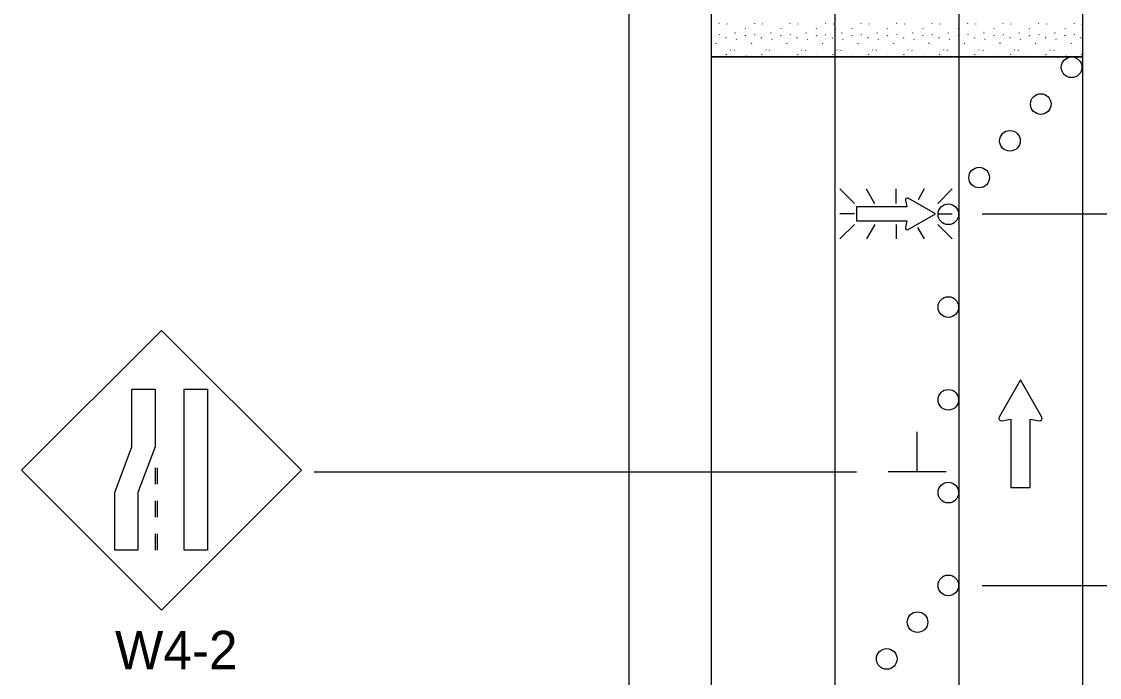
# Model space of a CAD drawing. Extents: x 16742 to 18475, y 7016 to 8203.
# Drawn here: x 16845.6 to 17054.7, y 7838.6 to 7965.9 of the extents above; entities that cross this region are included whole.
import ezdxf

# ---------------------------------------------------------------- set-up
doc = ezdxf.new("R2010")
doc.units = 0
for name, color, linetype in [('ALI_LEGAL_EX', 7, 'Continuous'), ('MT_SCRATCH_LEVEL_A', 7, 'Continuous'), ('MT_SCRATCH_LEVEL_E', 7, 'Continuous'), ('PAVT_EDGE_EX', 7, 'Continuous'), ('TRAFFIC_SIGNS_PR', 7, 'Continuous'), ('TYPICAL_TEXT_DIMEN_PR', 7, 'Continuous')]:
    doc.layers.add(name, color=color, linetype=linetype)

msp = doc.modelspace()

# ---------------------------------------------------------------- linework, layer by layer
at = {"layer": 'ALI_LEGAL_EX'}
for p, q in [((17003.37, 8174.11), (17003.37, 7344.93)), ((17027.37, 8174.11), (17027.37, 7344.93)), ((17051.37, 8174.11), (17051.37, 7344.93)), ((17051.37, 8174.11), (17051.37, 7344.93)), ((17003.37, 8073.55), (17003.37, 7244.36)), ((17027.37, 8073.55), (17027.37, 7244.36)), ((17051.37, 8073.55), (17051.37, 7244.36)), ((17051.37, 8073.55), (17051.37, 7244.36))]:
    msp.add_line(p, q, dxfattribs=at)
for points in [[(17003.37, 7891.2), (17003.37, 7866.2)], [(17027.37, 7891.2), (17027.37, 7866.2)], [(17051.37, 7891.2), (17051.37, 7866.2)]]:
    msp.add_lwpolyline(points, dxfattribs=at)
at = {"layer": 'MT_SCRATCH_LEVEL_A'}
for p, q in [((16979.37, 8103.02), (16979.37, 7959.05)), ((16979.37, 7988.11), (16979.37, 7959.05)), ((16980.86, 7965.57), (16980.91, 7965.5)), ((16982.39, 7965.43), (16982.44, 7965.36)), ((16987.75, 7965.57), (16987.8, 7965.5)), ((16989.28, 7965.43), (16989.33, 7965.36)), ((16994.64, 7965.57), (16994.69, 7965.5)), ((16996.17, 7965.43), (16996.22, 7965.36)), ((17001.53, 7965.57), (17001.58, 7965.5)), ((17003.06, 7965.43), (17003.11, 7965.36)), ((17008.41, 7965.57), (17008.46, 7965.5)), ((17009.94, 7965.43), (17009.99, 7965.36)), ((17015.3, 7965.57), (17015.35, 7965.5)), ((17016.83, 7965.43), (17016.88, 7965.36)), ((17022.19, 7965.57), (17022.24, 7965.5)), ((17023.72, 7965.43), (17023.77, 7965.36)), ((17029.08, 7965.57), (17029.13, 7965.5)), ((17030.6, 7965.43), (17030.66, 7965.36)), ((17035.96, 7965.57), (17036.01, 7965.5)), ((17037.49, 7965.43), (17037.54, 7965.36)), ((17042.85, 7965.57), (17042.9, 7965.5)), ((17044.38, 7965.43), (17044.43, 7965.36)), ((17049.74, 7965.57), (17049.79, 7965.5)), ((17051.27, 7965.43), (17051.32, 7965.36)), ((16980.91, 7963.36), (16980.96, 7963.29)), ((16982.19, 7962.79), (16982.21, 7962.67)), ((16984.03, 7963.65), (16984.08, 7963.76)), ((16985.96, 7964.52), (16986.01, 7964.44)), ((16986, 7963.11), (16986.05, 7963.23)), ((16987.8, 7963.36), (16987.85, 7963.29)), ((16989.08, 7962.79), (16989.09, 7962.67)), ((16990.92, 7963.65), (16990.97, 7963.76)), ((16992.85, 7964.52), (16992.9, 7964.44)), ((16992.89, 7963.11), (16992.94, 7963.23)), ((16994.69, 7963.36), (16994.74, 7963.29)), ((16995.97, 7962.79), (16995.98, 7962.67)), ((16997.81, 7963.65), (16997.86, 7963.76)), ((16999.73, 7964.52), (16999.79, 7964.44)), ((16999.78, 7963.11), (16999.83, 7963.23)), ((17001.57, 7963.36), (17001.62, 7963.29)), ((17002.85, 7962.79), (17002.87, 7962.67)), ((17004.7, 7963.65), (17004.75, 7963.76)), ((17006.62, 7964.52), (17006.67, 7964.44)), ((17006.66, 7963.11), (17006.72, 7963.23)), ((17008.46, 7963.36), (17008.51, 7963.29)), ((17009.74, 7962.79), (17009.76, 7962.67)), ((17011.58, 7963.65), (17011.64, 7963.76)), ((17013.51, 7964.52), (17013.56, 7964.44)), ((17013.55, 7963.11), (17013.6, 7963.23)), ((17015.35, 7963.36), (17015.4, 7963.29)), ((17016.63, 7962.79), (17016.64, 7962.67)), ((17018.47, 7963.65), (17018.52, 7963.76)), ((17020.4, 7964.52), (17020.45, 7964.44)), ((17020.44, 7963.11), (17020.49, 7963.23)), ((17022.24, 7963.36), (17022.29, 7963.29)), ((17023.52, 7962.79), (17023.53, 7962.67)), ((17025.36, 7963.65), (17025.41, 7963.76)), ((17027.28, 7964.52), (17027.34, 7964.44)), ((17027.33, 7963.11), (17027.38, 7963.23)), ((17029.12, 7963.36), (17029.17, 7963.29)), ((17030.4, 7962.79), (17030.42, 7962.67)), ((17032.25, 7963.65), (17032.3, 7963.76)), ((17034.17, 7964.52), (17034.22, 7964.44)), ((17034.21, 7963.11), (17034.27, 7963.23)), ((17036.01, 7963.36), (17036.06, 7963.29)), ((17037.29, 7962.79), (17037.31, 7962.67)), ((17039.13, 7963.65), (17039.19, 7963.76)), ((17041.06, 7964.52), (17041.11, 7964.44)), ((17041.1, 7963.11), (17041.15, 7963.23)), ((17042.9, 7963.36), (17042.95, 7963.29)), ((17044.18, 7962.79), (17044.19, 7962.67)), ((17046.02, 7963.65), (17046.07, 7963.76)), ((17047.95, 7964.52), (17048, 7964.44)), ((17047.99, 7963.11), (17048.04, 7963.23)), ((17049.79, 7963.36), (17049.84, 7963.29)), ((17051.07, 7962.79), (17051.08, 7962.67)), ((16980.29, 7961.61), (16980.34, 7961.73)), ((16984.22, 7962.45), (16984.27, 7962.37)), ((16987.18, 7961.61), (16987.23, 7961.73)), ((16991.11, 7962.45), (16991.16, 7962.37)), ((16994.07, 7961.61), (16994.12, 7961.73)), ((16998, 7962.45), (16998.05, 7962.37)), ((17000.96, 7961.61), (17001.01, 7961.73)), ((17004.89, 7962.45), (17004.94, 7962.37)), ((17007.84, 7961.61), (17007.89, 7961.73)), ((17011.77, 7962.45), (17011.82, 7962.37)), ((17014.73, 7961.61), (17014.78, 7961.73)), ((17018.66, 7962.45), (17018.71, 7962.37)), ((17021.62, 7961.61), (17021.67, 7961.73)), ((17025.55, 7962.45), (17025.6, 7962.37)), ((17028.51, 7961.61), (17028.56, 7961.73)), ((17032.44, 7962.45), (17032.49, 7962.37)), ((17035.39, 7961.61), (17035.44, 7961.73)), ((17039.32, 7962.45), (17039.37, 7962.37)), ((17042.28, 7961.61), (17042.33, 7961.73)), ((17046.21, 7962.45), (17046.26, 7962.37)), ((17049.17, 7961.61), (17049.22, 7961.73)), ((17051.37, 7959.05), (16979.37, 7959.05)), ((16979.37, 7959.05), (17051.37, 7959.05)), ((16982.31, 7959.42), (16982.36, 7959.53)), ((16983.08, 7960.38), (16983.13, 7960.3)), ((16983.81, 7960.35), (16983.87, 7960.27)), ((16986.13, 7959.12), (16986.18, 7959.24)), ((16989.2, 7959.42), (16989.25, 7959.53)), ((16989.96, 7960.38), (16990.01, 7960.3)), ((16990.7, 7960.35), (16990.75, 7960.27)), ((16993.02, 7959.12), (16993.07, 7959.24)), ((16996.09, 7959.42), (16996.14, 7959.53)), ((16996.85, 7960.38), (16996.9, 7960.3)), ((16997.59, 7960.35), (16997.64, 7960.27)), ((16999.91, 7959.12), (16999.96, 7959.24)), ((17002.97, 7959.42), (17003.03, 7959.53)), ((17003.74, 7960.38), (17003.79, 7960.3)), ((17004.48, 7960.35), (17004.53, 7960.27)), ((17006.79, 7959.12), (17006.85, 7959.24)), ((17009.86, 7959.42), (17009.91, 7959.53)), ((17010.63, 7960.38), (17010.68, 7960.3)), ((17011.36, 7960.35), (17011.42, 7960.27)), ((17013.68, 7959.12), (17013.73, 7959.24)), ((17016.75, 7959.42), (17016.8, 7959.53)), ((17017.51, 7960.38), (17017.56, 7960.3)), ((17018.25, 7960.35), (17018.3, 7960.27)), ((17020.57, 7959.12), (17020.62, 7959.24)), ((17023.64, 7959.42), (17023.69, 7959.53)), ((17024.4, 7960.38), (17024.45, 7960.3)), ((17025.14, 7960.35), (17025.19, 7960.27)), ((17027.46, 7959.12), (17027.51, 7959.24)), ((17030.53, 7959.42), (17030.58, 7959.53)), ((17031.29, 7960.38), (17031.34, 7960.3)), ((17032.03, 7960.35), (17032.08, 7960.27)), ((17034.34, 7959.12), (17034.4, 7959.24)), ((17037.41, 7959.42), (17037.46, 7959.53)), ((17038.18, 7960.38), (17038.23, 7960.3)), ((17038.91, 7960.35), (17038.97, 7960.27)), ((17041.23, 7959.12), (17041.28, 7959.24)), ((17044.3, 7959.42), (17044.35, 7959.53)), ((17045.06, 7960.38), (17045.12, 7960.3)), ((17045.8, 7960.35), (17045.85, 7960.27)), ((17048.12, 7959.12), (17048.17, 7959.24)), ((17051.19, 7959.42), (17051.24, 7959.53))]:
    msp.add_line(p, q, dxfattribs=at)
at = {"layer": 'MT_SCRATCH_LEVEL_E'}
for p, q in [((17039.33, 7896.35), (17035.22, 7889.11)), ((17039.33, 7896.35), (17035.22, 7889.11)), ((17043.48, 7889.11), (17039.33, 7896.35)), ((17043.48, 7889.11), (17039.33, 7896.35)), ((17035.7, 7888.42), (17037.48, 7888.74)), ((17035.7, 7888.42), (17037.48, 7888.74)), ((17037.48, 7888.74), (17037.48, 7875.48)), ((17037.48, 7888.74), (17037.48, 7875.48)), ((17041.22, 7875.48), (17041.22, 7888.74)), ((17041.22, 7888.74), (17043, 7888.42)), ((17041.22, 7875.48), (17041.22, 7888.74)), ((17041.22, 7888.74), (17043, 7888.42)), ((17037.48, 7875.48), (17041.22, 7875.48)), ((17037.48, 7875.48), (17041.22, 7875.48))]:
    msp.add_line(p, q, dxfattribs=at)
for centre, start, end in [((17035.63, 7888.88), 150.4248, 279.9638), ((17035.63, 7888.88), 150.4248, 279.9638), ((17043.07, 7888.88), 260.0362, 29.7731), ((17043.07, 7888.88), 260.0362, 29.7731)]:
    msp.add_arc(centre, 0.463, start, end, dxfattribs=at)
at = {"layer": 'PAVT_EDGE_EX'}
for p, q in [((16963.37, 8203.06), (16963.37, 7352.47)), ((16979.37, 8203.06), (16979.37, 7352.47))]:
    msp.add_line(p, q, dxfattribs=at)
at = {"layer": 'TRAFFIC_SIGNS_PR'}
for p, q in [((17007.14, 7930.59), (17004.32, 7933.41)), ((17009.44, 7933.41), (17011.06, 7930.59)), ((17015.22, 7930.59), (17015.22, 7933.41)), ((17020.69, 7933.41), (17019.49, 7931.32)), ((17026.13, 7933.41), (17023.31, 7930.59)), ((17007.14, 7928.56), (17004.32, 7928.56)), ((17023.31, 7928.56), (17026.13, 7928.56)), ((17007.14, 7926.53), (17004.32, 7923.7)), ((17011.09, 7926.53), (17009.46, 7923.71)), ((17015.22, 7926.53), (17015.22, 7923.71)), ((17019.41, 7925.89), (17020.67, 7923.71)), ((17026.13, 7923.71), (17023.31, 7926.53)), ((16872.77, 7905.97), (16845.62, 7878.82)), ((16899.92, 7878.82), (16872.77, 7905.97)), ((16871.52, 7879.31), (16871.52, 7876.11)), ((16871.92, 7879.31), (16871.92, 7876.11)), ((16845.62, 7878.82), (16872.77, 7851.66)), ((16872.77, 7851.66), (16899.92, 7878.82)), ((16871.52, 7872.91), (16871.52, 7869.71)), ((16871.92, 7872.91), (16871.92, 7869.71)), ((16871.52, 7866.51), (16871.52, 7863.31)), ((16871.92, 7866.51), (16871.92, 7863.31))]:
    msp.add_line(p, q, dxfattribs=at)
for points in [[(17017.55, 7925.54), (17022.86, 7928.56), (17017.55, 7931.6)], [(17017.05, 7931.24), (17017.28, 7929.94), (17007.56, 7929.94), (17007.56, 7927.2), (17017.28, 7927.2), (17017.05, 7925.9)]]:
    msp.add_lwpolyline(points, dxfattribs=at)
for points in [[(16871.52, 7894.55), (16871.52, 7883.37), (16868.18, 7874.49), (16868.18, 7863.31), (16863.69, 7863.31), (16863.69, 7874.49), (16867.03, 7883.37), (16867.03, 7894.55)], [(16881.66, 7894.55), (16881.66, 7863.31), (16877.17, 7863.31), (16877.17, 7894.55)]]:
    msp.add_lwpolyline(points, close=True, dxfattribs=at)
for centre in [(17049.27, 7957), (17049.27, 7957), (17043.29, 7949.87), (17037.31, 7942.74), (17031.34, 7935.61), (17025.36, 7928.49), (17025.36, 7910.49), (17025.36, 7892.49), (17025.36, 7874.49), (17025.36, 7856.49), (17025.36, 7856.49), (17019.39, 7849.36), (17013.41, 7842.23)]:
    msp.add_circle(centre, 2, dxfattribs=at)
for centre, start, end in [((17017.39, 7931.3), 61.4833, 189.9593), ((17017.39, 7925.84), 170.7308, 298.8916)]:
    msp.add_arc(centre, 0.341, start, end, dxfattribs=at)
at = {"layer": 'TYPICAL_TEXT_DIMEN_PR'}
for p, q in [((17167.41, 7928.49), (17031.9, 7928.49)), ((17019.29, 7878.49), (17019.29, 7886.27)), ((16902.39, 7878.49), (17007.56, 7878.49)), ((17024.92, 7878.49), (17013.67, 7878.49)), ((17031.9, 7856.49), (17167.41, 7856.49))]:
    msp.add_line(p, q, dxfattribs=at)

# ---------------------------------------------------------------- texts
at = {"layer": 'TRAFFIC_SIGNS_PR'}
msp.add_text('W4-2', height=7.44, dxfattribs=at).set_placement((16863.73, 7840.23))

doc.saveas('drawing.dxf')
